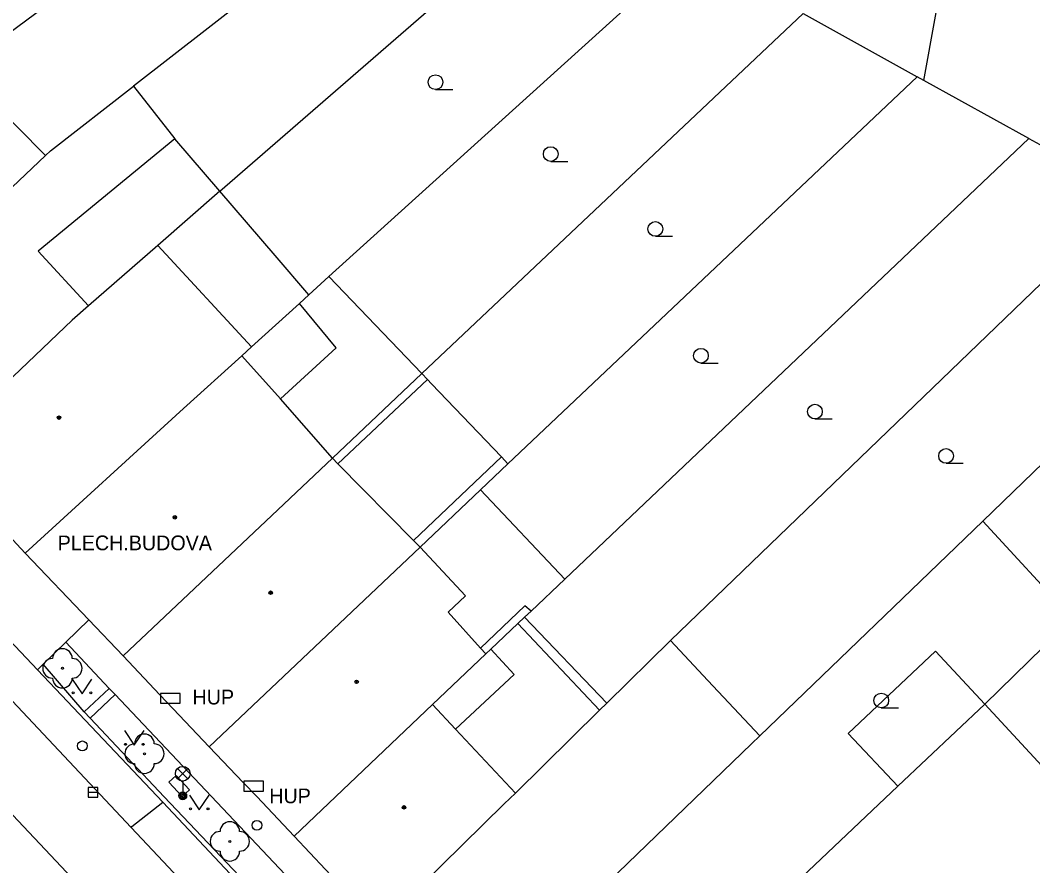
# Model space of a CAD drawing. Extents: x -596229 to -595156, y -1161237 to -1159376.
# Drawn here: x -596025.5 to -595973.9, y -1160530.5 to -1160487.4 of the extents above; entities that cross this region are included whole.
import ezdxf

# ---------------------------------------------------------------- set-up
doc = ezdxf.new("R2010")
doc.units = 0
for name, color, linetype in [('DOP - kresba z DSPS bez souradnic', 7, 'Continuous'), ('DOP - rozhrani ploch obecne', 7, 'Continuous'), ('Level 22', 7, 'Continuous'), ('Level 24', 7, 'Continuous'), ('Level 27', 7, 'Continuous'), ('Level 28', 7, 'Continuous'), ('Level 33', 7, 'Continuous'), ('Level 36', 7, 'Continuous'), ('Level 39', 7, 'Continuous'), ('slaboproud - povrch.  znaky a tel. budka skut. velikost', 7, 'Continuous'), ('Specificka linie pasportu komunikaci', 7, 'Continuous'), ('TM - budovy zdene_ betonove - VP', 7, 'Continuous'), ('TM - chodniky - VP', 7, 'Continuous'), ('TM - komunikace - VP', 7, 'Continuous'), ('TM - letecke snimky - pomocna linie', 7, 'Continuous'), ('TM - popis objektu', 7, 'Continuous'), ('TM - rozhrani ploch obecne - VP', 7, 'Continuous')]:
    doc.layers.add(name, color=color, linetype=linetype)

msp = doc.modelspace()

# ---------------------------------------------------------------- linework, layer by layer
at = {"layer": 'DOP - kresba z DSPS bez souradnic'}
for points in [[(-596009.44, -1160504.11), (-596011.3, -1160501.86)], [(-596012.26, -1160506.71), (-596009.44, -1160504.11)], [(-596004.78, -1160505.73), (-596009.34, -1160510.02)], [(-596001.01, -1160509.66), (-596005.49, -1160513.92)], [(-596002.08, -1160519.4), (-595999.82, -1160517.25)], [(-595999.5, -1160517.52), (-595999.82, -1160517.25)], [(-596000.17, -1160518.15), (-595996.01, -1160522.56)], [(-596000.36, -1160520.74), (-596001.55, -1160519.45)], [(-596003.36, -1160523.52), (-596000.36, -1160520.74)]]:
    msp.add_lwpolyline(points, dxfattribs=at)
at = {"layer": 'DOP - rozhrani ploch obecne'}
for points in [[(-595979.49, -1160490.51), (-595975.54, -1160468.69)], [(-596026.59, -1160488.43), (-596008.04, -1160474.71)], [(-596002.8, -1160477.61), (-596019.75, -1160490.79)], [(-596015.36, -1160496.14), (-595997.43, -1160480.58)], [(-595991.45, -1160483.89), (-596009.8, -1160500.49)], [(-596005.07, -1160505.43), (-595985.64, -1160487.1)], [(-595985.64, -1160487.1), (-595979.83, -1160490.32)], [(-595979.83, -1160490.32), (-596000.68, -1160510.02)], [(-595979.49, -1160490.51), (-595979.83, -1160490.32)], [(-595974.14, -1160493.46), (-595979.49, -1160490.51)], [(-596015.36, -1160496.14), (-596017.65, -1160493.48)], [(-595997.78, -1160515.89), (-595974.14, -1160493.46)], [(-595974.14, -1160493.46), (-595973.4, -1160493.87)], [(-596015.36, -1160496.14), (-596018.52, -1160498.9)], [(-596012.54, -1160499.42), (-596015.36, -1160496.14)], [(-595992.39, -1160519.01), (-595971.21, -1160498.61)], [(-596010.82, -1160501.42), (-596012.54, -1160499.42)], [(-596009.8, -1160500.49), (-596010.82, -1160501.42)], [(-596009.8, -1160500.49), (-596005.07, -1160505.43)], [(-596010.82, -1160501.42), (-596011.3, -1160501.86)], [(-596011.3, -1160501.86), (-596013.74, -1160504.07)], [(-596009.62, -1160509.73), (-596005.07, -1160505.43)], [(-596004.78, -1160505.73), (-596005.07, -1160505.43)], [(-596004.58, -1160505.94), (-596004.78, -1160505.73)], [(-596001.01, -1160509.66), (-596004.58, -1160505.94)], [(-595969.3, -1160506), (-595976.49, -1160512.94)], [(-596000.68, -1160510.02), (-596001.01, -1160509.66)], [(-596002.08, -1160511.34), (-596000.68, -1160510.02)], [(-596005.16, -1160514.26), (-596002.08, -1160511.34)], [(-595976.49, -1160512.94), (-595987.84, -1160523.87)], [(-595971.92, -1160517.89), (-595976.49, -1160512.94)], [(-595999.5, -1160517.52), (-595997.78, -1160515.89)], [(-595999.84, -1160517.83), (-596000.17, -1160518.15)], [(-595999.84, -1160517.83), (-595999.5, -1160517.52)], [(-595995.64, -1160522.2), (-595999.84, -1160517.83)], [(-595971.92, -1160517.89), (-595976.39, -1160522.25)], [(-596000.17, -1160518.15), (-596001.55, -1160519.45)], [(-596001.55, -1160519.45), (-596001.81, -1160519.7)]]:
    msp.add_lwpolyline(points, dxfattribs=at)
at = {"layer": 'Level 22'}
for centre in [(-596023.38, -1160520.43), (-596019.2, -1160524.78), (-596014.85, -1160529.24)]:
    msp.add_circle(centre, 0.05, dxfattribs=at)
for centre, start, end in [((-596023.38, -1160519.93), 0, 180), ((-596023.88, -1160520.43), 90, 270), ((-596022.88, -1160520.43), 270, 90), ((-596023.38, -1160520.93), 180, 0), ((-596019.2, -1160524.28), 0, 180), ((-596019.7, -1160524.78), 90, 270), ((-596018.7, -1160524.78), 270, 90), ((-596019.2, -1160525.28), 180, 0), ((-596014.85, -1160528.74), 0, 180), ((-596015.35, -1160529.24), 90, 270), ((-596014.35, -1160529.24), 270, 90), ((-596014.85, -1160529.74), 180, 0)]:
    msp.add_arc(centre, 0.5, start, end, dxfattribs=at)
at = {"layer": 'Level 24'}
for points in [[(-596018.378, -1160522.209), (-596017.378, -1160522.209), (-596017.378, -1160521.709), (-596018.378, -1160521.709)], [(-596014.138, -1160526.679), (-596013.138, -1160526.679), (-596013.138, -1160526.179), (-596014.138, -1160526.179)]]:
    msp.add_lwpolyline(points, close=True, dxfattribs=at)
at = {"layer": 'Level 27'}
msp.add_line((-596022.07, -1160526.74), (-596021.57, -1160526.74), dxfattribs=at)
msp.add_lwpolyline([(-596022.07, -1160526.99), (-596021.57, -1160526.99), (-596021.57, -1160526.49), (-596022.07, -1160526.49)], close=True, dxfattribs=at)
at = {"layer": 'Level 28'}
for centre in [(-596022.36, -1160524.38), (-596013.47, -1160528.42)]:
    msp.add_circle(centre, 0.25, dxfattribs=at)
at = {"layer": 'Level 33'}
for p, q in [((-596017.515, -1160526.06), (-596016.985, -1160525.53)), ((-596017.515, -1160525.53), (-596016.985, -1160526.06)), ((-596017.25, -1160526.17), (-596017.25, -1160526.92))]:
    msp.add_line(p, q, dxfattribs=at)
for centre, radius in [((-596017.25, -1160525.795), 0.375), ((-596017.25, -1160526.92), 0.2), ((-596017.25, -1160526.92), 0.145), ((-596017.25, -1160526.92), 0.0876)]:
    msp.add_circle(centre, radius, dxfattribs=at)
at = {"layer": 'Level 36'}
for p, q in [((-596004.37, -1160490.965), (-596003.495, -1160490.965)), ((-595998.5, -1160494.625), (-595997.625, -1160494.625)), ((-595993.17, -1160498.435), (-595992.295, -1160498.435)), ((-595990.85, -1160504.895), (-595989.975, -1160504.895)), ((-595985.04, -1160507.735), (-595984.165, -1160507.735)), ((-595978.36, -1160509.995), (-595977.485, -1160509.995)), ((-595981.66, -1160522.445), (-595980.785, -1160522.445))]:
    msp.add_line(p, q, dxfattribs=at)
for points in [[(-596022.88, -1160520.98), (-596022.38, -1160521.73), (-596021.88, -1160520.98)], [(-596020.22, -1160523.6), (-596019.72, -1160524.35), (-596019.22, -1160523.6)], [(-596016.91, -1160526.89), (-596016.41, -1160527.64), (-596015.91, -1160526.89)]]:
    msp.add_lwpolyline(points, dxfattribs=at)
for centre, radius in [((-596004.37, -1160490.59), 0.375), ((-595998.5, -1160494.25), 0.375), ((-595993.17, -1160498.06), 0.375), ((-595990.85, -1160504.52), 0.375), ((-595985.04, -1160507.36), 0.375), ((-595978.36, -1160509.62), 0.375), ((-596022.83, -1160521.68), 0.05), ((-596021.931, -1160521.68), 0.05), ((-595981.66, -1160522.07), 0.375), ((-596020.17, -1160524.3), 0.05), ((-596019.271, -1160524.3), 0.05), ((-596016.86, -1160527.59), 0.05), ((-596015.961, -1160527.59), 0.05)]:
    msp.add_circle(centre, radius, dxfattribs=at)
at = {"layer": 'Level 39'}
for centre, radius in [((-596023.55, -1160507.67), 0.09), ((-596023.55, -1160507.67), 0.0398), ((-596017.65, -1160512.74), 0.09), ((-596017.65, -1160512.74), 0.0398), ((-596012.77, -1160516.58), 0.09), ((-596012.77, -1160516.58), 0.0398), ((-596008.39, -1160521.12), 0.09), ((-596008.39, -1160521.12), 0.0398), ((-596005.98, -1160527.51), 0.09), ((-596005.98, -1160527.51), 0.0398)]:
    msp.add_circle(centre, radius, dxfattribs=at)
at = {"layer": 'slaboproud - povrch.  znaky a tel. budka skut. velikost'}
msp.add_lwpolyline([(-596017.95, -1160526.23), (-596017.58, -1160525.88), (-596016.9, -1160526.62), (-596017.27, -1160526.96), (-596017.95, -1160526.23)], dxfattribs=at)
at = {"layer": 'Specificka linie pasportu komunikaci'}
for points in [[(-596022.27, -1160522.65), (-596021.97, -1160522.97)], [(-596019.88, -1160528.53), (-596019.84, -1160528.49), (-596018.26, -1160527.25)]]:
    msp.add_lwpolyline(points, dxfattribs=at)
at = {"layer": 'TM - budovy zdene_ betonove - VP'}
for points in [[(-596023.99, -1160494.09), (-596019.75, -1160490.79)], [(-596019.75, -1160490.79), (-596017.65, -1160493.48)], [(-596017.65, -1160493.48), (-596024.61, -1160499.2)], [(-596024.24, -1160494.32), (-596023.99, -1160494.09)], [(-596027.97, -1160497.86), (-596024.24, -1160494.32)], [(-596024.61, -1160499.2), (-596022.05, -1160501.97)], [(-596018.52, -1160498.9), (-596022.05, -1160501.97)], [(-596013.74, -1160504.07), (-596018.52, -1160498.9)], [(-596022.05, -1160501.97), (-596022.89, -1160502.71)], [(-596022.89, -1160502.71), (-596030.05, -1160509.52)], [(-596014.24, -1160504.52), (-596017.21, -1160507.2)], [(-596014.24, -1160504.52), (-596013.74, -1160504.07)], [(-596012.26, -1160506.71), (-596014.24, -1160504.52)], [(-596009.62, -1160509.73), (-596012.26, -1160506.71)], [(-596017.21, -1160507.2), (-596025.27, -1160514.56)], [(-596012.41, -1160512.36), (-596009.62, -1160509.73)], [(-596009.62, -1160509.73), (-596009.34, -1160510.02)], [(-596009.34, -1160510.02), (-596005.49, -1160513.92)], [(-596025.27, -1160514.56), (-596027.22, -1160512.5)], [(-596020.29, -1160519.8), (-596012.41, -1160512.36)], [(-596015.91, -1160524.42), (-596005.16, -1160514.26)], [(-596005.49, -1160513.92), (-596005.16, -1160514.26)], [(-596005.16, -1160514.26), (-596002.84, -1160516.74)], [(-596022.04, -1160517.96), (-596025.27, -1160514.56)], [(-596002.84, -1160516.74), (-596003.73, -1160517.57)], [(-596020.29, -1160519.8), (-596022.04, -1160517.96)], [(-596003.73, -1160517.57), (-596002.08, -1160519.4)], [(-596002.08, -1160519.4), (-596001.81, -1160519.7)], [(-595992.39, -1160519.01), (-595995.64, -1160522.2)], [(-595992.39, -1160519.01), (-595990.49, -1160521.05)], [(-596015.91, -1160524.42), (-596017.73, -1160522.5), (-596018.42, -1160521.78), (-596020.29, -1160519.8)], [(-596001.81, -1160519.7), (-596004.52, -1160522.27)], [(-595990.49, -1160521.05), (-595987.84, -1160523.87)], [(-596011.58, -1160528.97), (-596004.52, -1160522.27)], [(-596004.52, -1160522.27), (-596003.36, -1160523.52)], [(-595996.01, -1160522.56), (-596000.3, -1160526.78)], [(-595995.64, -1160522.2), (-595996.01, -1160522.56)], [(-595980.81, -1160526.43), (-595976.39, -1160522.25)], [(-595976.39, -1160522.25), (-595969.74, -1160529.43)], [(-596003.36, -1160523.52), (-596000.3, -1160526.78)], [(-595987.84, -1160523.87), (-595988.27, -1160524.28)], [(-596011.58, -1160528.97), (-596013.48, -1160526.96), (-596014.17, -1160526.24), (-596015.91, -1160524.42)], [(-595988.27, -1160524.28), (-596002.82, -1160538.31)], [(-595986.35, -1160531.67), (-595980.81, -1160526.43)], [(-596000.3, -1160526.78), (-596000.87, -1160527.33)], [(-596007.24, -1160533.59), (-596000.87, -1160527.33)], [(-596007.24, -1160533.59), (-596008.49, -1160532.25), (-596009.18, -1160531.52), (-596011.58, -1160528.97)]]:
    msp.add_lwpolyline(points, dxfattribs=at)
at = {"layer": 'TM - chodniky - VP'}
for points in [[(-596024.36, -1160520.22), (-596023.21, -1160519.1)], [(-596023.21, -1160519.1), (-596020.99, -1160521.45)], [(-596024.65, -1160520.51), (-596024.36, -1160520.22)], [(-596022.27, -1160522.65), (-596024.36, -1160520.22)], [(-596022.27, -1160522.65), (-596020.99, -1160521.45)], [(-596020.99, -1160521.45), (-596020.69, -1160521.77)], [(-596021.97, -1160522.97), (-596020.69, -1160521.77)], [(-596020.69, -1160521.77), (-596010.89, -1160532.13)], [(-596018.19, -1160526.97), (-596021.97, -1160522.97)], [(-596012.14, -1160533.36), (-596018.19, -1160526.97)]]:
    msp.add_lwpolyline(points, dxfattribs=at)
at = {"layer": 'TM - komunikace - VP'}
for points in [[(-596024.65, -1160520.51), (-596029.84, -1160515.03)], [(-596018.26, -1160527.25), (-596024.65, -1160520.51)], [(-596003.85, -1160542.58), (-596005.38, -1160540.95), (-596018.26, -1160527.25)]]:
    msp.add_lwpolyline(points, dxfattribs=at)
at = {"layer": 'TM - letecke snimky - pomocna linie'}
for points in [[(-596024.24, -1160494.32), (-596028.53, -1160489.99)], [(-596002.08, -1160511.34), (-595997.78, -1160515.89)], [(-595976.39, -1160522.25), (-595978.89, -1160519.55), (-595983.34, -1160523.75), (-595980.81, -1160526.43)]]:
    msp.add_lwpolyline(points, dxfattribs=at)
at = {"layer": 'TM - rozhrani ploch obecne - VP'}
for points in [[(-596019.88, -1160528.53), (-596030.95, -1160516.77)], [(-596023.21, -1160519.1), (-596022.04, -1160517.96)], [(-595982.49, -1160573.92), (-596022.63, -1160531.38), (-596031.1, -1160522.41)], [(-596012.03, -1160536.87), (-596019.88, -1160528.53)]]:
    msp.add_lwpolyline(points, dxfattribs=at)

# ---------------------------------------------------------------- texts
at = {"layer": 'TM - popis objektu'}
for s, p in [('PLECH.BUDOVA', (-596023.62, -1160514.42)), ('HUP', (-596016.75, -1160522.27)), ('HUP', (-596012.84, -1160527.3))]:
    msp.add_text(s, height=0.75, dxfattribs=at).set_placement(p)

doc.saveas('drawing.dxf')
